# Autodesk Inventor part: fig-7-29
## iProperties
Shininess: 77.0
Length Units: 11269
Angle Units: 11279
Time Units: 11290
Mass Units: 11283
Length Display Precision: 3
Angle Display Precision: 2
Created: 2002-01
Part Number: fig-7-29
Document SubType Name: Modeling
Designer: CADSoft
Density: 1 g/cm^3
Density: 0.0
Volumn: 0.0
Area: 0.0
PropertySet Name: Model Information
Control State: 0
Master: False
Checked Out: False
Author: CADSoft
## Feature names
1. Extrusion2
2. Coil6
